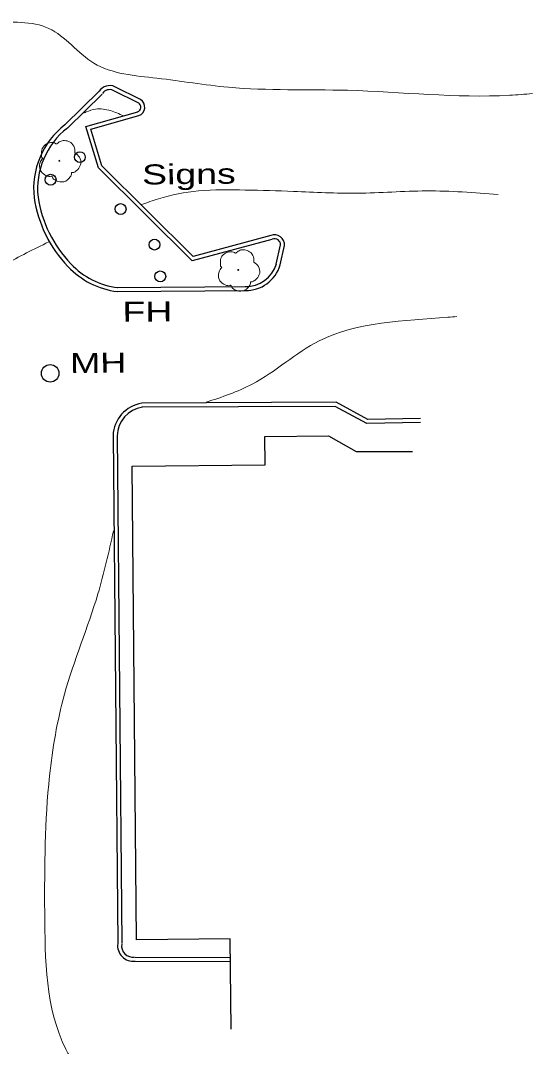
# Model space of a CAD drawing. Extents: x 2361708 to 2370558, y 6977955 to 6991887.
# Drawn here: x 2367606.3 to 2367729.2, y 6988537.8 to 6988783.9 of the extents above; entities that cross this region are included whole.
import ezdxf

# ---------------------------------------------------------------- set-up
doc = ezdxf.new("R2010")
doc.units = 0
doc.header["$LTSCALE"] = 1.9
for name, color, linetype, lineweight in [('11', 7, 'Continuous', 25), ('2', 7, 'Continuous', 25), ('20', 7, 'Continuous', 25), ('21', 7, 'Continuous', 25), ('29', 7, 'Continuous', 13), ('35', 7, 'Continuous', 13)]:
    doc.layers.add(name, color=color, linetype=linetype, lineweight=lineweight)

msp = doc.modelspace()

# ---------------------------------------------------------------- linework, layer by layer
at = {"layer": '11'}
for p, q in [((2367680.208, 6988684.291), (2367686.865, 6988680.534)), ((2367686.865, 6988680.534), (2367700.365, 6988680.552))]:
    msp.add_line(p, q, dxfattribs=at)
msp.add_lwpolyline([(2367656.812, 6988541.951), (2367656.606, 6988563.6), (2367634.167, 6988563.386), (2367633.085, 6988677.052), (2367664.994, 6988677.355), (2367664.929, 6988684.145), (2367680.228, 6988684.291)], dxfattribs=at)
at = {"layer": '2'}
for p, q in [((2367635.108, 6988764.975), (2367628.929, 6988768.046)), ((2367625.179, 6988766.971), (2367616.955, 6988758.902)), ((2367625.856, 6988766.287), (2367617.632, 6988758.218)), ((2367634.677, 6988764.111), (2367628.497, 6988767.182)), ((2367667.675, 6988725.513), (2367668.702, 6988730.133)), ((2367668.618, 6988725.302), (2367669.643, 6988729.922)), ((2367629.497, 6988719.88), (2367661.017, 6988720.14)), ((2367629.506, 6988718.919), (2367661.026, 6988719.18)), ((2367628.505, 6988684.379), (2367629.625, 6988562.493)), ((2367629.465, 6988684.388), (2367630.585, 6988562.502)), ((2367633.786, 6988558.292), (2367656.518, 6988558.199)), ((2367633.787, 6988559.253), (2367656.418, 6988559.158))]:
    msp.add_line(p, q, dxfattribs=at)
for points in [[(2367666.579, 6988731.423), (2367647.487, 6988726.281), (2367624.994, 6988748.558), (2367621.939, 6988758.519), (2367634.426, 6988762.058)], [(2367666.33, 6988732.351), (2367647.767, 6988727.354), (2367625.839, 6988749.066), (2367623.145, 6988757.861), (2367634.685, 6988761.131)], [(2367702.26, 6988688.471), (2367689.631, 6988688.21), (2367682.062, 6988692.339), (2367635.382, 6988692.104)], [(2367702.269, 6988687.511), (2367689.401, 6988687.248), (2367681.821, 6988691.376), (2367635.391, 6988691.144)]]:
    msp.add_lwpolyline(points, dxfattribs=at)
for centre, radius, start, end in [((2367627.684, 6988765.315), 3.002, 65.50588, 146.54301), ((2367627.684, 6988765.315), 2.042, 65.50588, 146.54301), ((2367633.976, 6988763.154), 2.144, 289.30778, 58.12454), ((2367633.976, 6988763.154), 1.184, 289.30778, 58.12454), ((2367628.945, 6988743.516), 19.506, 127.9287, 186.13826), ((2367628.945, 6988743.516), 18.546, 127.9287, 186.13826), ((2367639.582, 6988745.968), 30.371, 188.59108, 223.87594), ((2367639.582, 6988745.968), 29.411, 188.59108, 223.87594), ((2367667.254, 6988730.136), 2.4, 354.89919, 112.62545), ((2367667.254, 6988730.136), 1.44, 354.89919, 112.62545), ((2367631.868, 6988738.213), 18.478, 223.1592, 263.02231), ((2367660.344, 6988727.789), 7.679, 268.81911, 343.27246), ((2367631.868, 6988738.213), 19.438, 223.1592, 263.02231), ((2367660.344, 6988727.789), 8.639, 268.81911, 343.27246), ((2367636.679, 6988684.027), 8.181, 99.1217, 177.53624), ((2367636.679, 6988684.027), 7.221, 99.1217, 177.53624), ((2367633.32, 6988561.992), 3.728, 172.27349, 277.17632), ((2367633.32, 6988561.992), 2.768, 172.27349, 277.17632)]:
    msp.add_arc(centre, radius, start, end, dxfattribs=at)
at = {"layer": '20'}
for centre, radius in [((2367639.832, 6988722.548), 1.3), ((2367613.412, 6988699.296), 2.1)]:
    msp.add_circle(centre, radius, dxfattribs=at)
at = {"layer": '21'}
for centre in [(2367620.539, 6988751.156), (2367613.53, 6988745.739), (2367630.328, 6988738.698), (2367638.45, 6988730.175)]:
    msp.add_circle(centre, 1.3, dxfattribs=at)
at = {"layer": '29'}
for centre in [(2367615.607, 6988750.299), (2367658.549, 6988724.096)]:
    msp.add_circle(centre, 0.1, dxfattribs=at)
for points in [[(2367611.642, 6988750.871), (2367611.661, 6988750.881), (2367611.581, 6988750.951), (2367611.345, 6988751.578), (2367611.383, 6988752.859), (2367612.27, 6988754.157), (2367613.576, 6988754.639), (2367614.697, 6988754.45), (2367614.929, 6988754.322), (2367614.999, 6988754.323), (2367615.048, 6988754.364), (2367615.396, 6988754.657), (2367616.261, 6988755.105), (2367617.472, 6988755.037), (2367618.588, 6988754.447), (2367619.321, 6988753.025), (2367619.33, 6988752.164)], [(2367619.319, 6988752.184), (2367620.46, 6988751.125), (2367620.745, 6988749.538), (2367620.037, 6988748.211), (2367619.382, 6988747.665), (2367618.714, 6988747.448), (2367618.565, 6988747.437), (2367618.545, 6988747.326), (2367618.224, 6988746.424), (2367616.685, 6988745.259), (2367614.793, 6988745.541), (2367613.893, 6988746.482), (2367613.822, 6988746.612), (2367613.702, 6988746.591), (2367612.491, 6988746.709), (2367611.222, 6988747.707), (2367610.876, 6988749.344), (2367611.246, 6988750.367), (2367611.572, 6988750.811), (2367611.642, 6988750.861)], [(2367654.583, 6988724.669), (2367654.603, 6988724.679), (2367654.522, 6988724.748), (2367654.286, 6988725.376), (2367654.324, 6988726.656), (2367655.212, 6988727.955), (2367656.517, 6988728.437), (2367657.639, 6988728.248), (2367657.87, 6988728.12), (2367657.94, 6988728.121), (2367657.99, 6988728.161), (2367658.337, 6988728.454), (2367659.203, 6988728.903), (2367660.414, 6988728.834), (2367661.529, 6988728.245), (2367662.263, 6988726.822), (2367662.271, 6988725.962)], [(2367662.261, 6988725.982), (2367663.401, 6988724.923), (2367663.686, 6988723.335), (2367662.979, 6988722.009), (2367662.324, 6988721.462), (2367661.656, 6988721.246), (2367661.506, 6988721.234), (2367661.487, 6988721.124), (2367661.166, 6988720.221), (2367659.626, 6988719.056), (2367657.734, 6988719.338), (2367656.835, 6988720.28), (2367656.764, 6988720.409), (2367656.644, 6988720.388), (2367655.433, 6988720.507), (2367654.163, 6988721.505), (2367653.818, 6988723.141), (2367654.188, 6988724.165), (2367654.514, 6988724.608), (2367654.583, 6988724.658)]]:
    msp.add_spline(points, degree=3, dxfattribs=at)
at = {"layer": '35'}
for points in [[(2367729.15, 6988766.39), (2367723.693, 6988765.998), (2367684.8, 6988767.188), (2367656.191, 6988767.926), (2367639.03, 6988770.093), (2367623.884, 6988773.739), (2367613.085, 6988782.047), (2367599.332, 6988783.376), (2367583.908, 6988783.609)], [(2367630.955, 6988761.085), (2367627.893, 6988762.316), (2367624.319, 6988762.673), (2367622.066, 6988762.001), (2367621.14, 6988761.622)], [(2367720.889, 6988742.221), (2367703.72, 6988743.057), (2367687.115, 6988742.499), (2367671.83, 6988742.954), (2367660.236, 6988743.263), (2367648.998, 6988743.046), (2367639.385, 6988741.165), (2367635.368, 6988739.766)], [(2367613.063, 6988730.804), (2367602.524, 6988725.293), (2367594.829, 6988719.52), (2367589.098, 6988713.345), (2367584.575, 6988707.311), (2367583.004, 6988704.286)], [(2367711.017, 6988712.935), (2367708.819, 6988712.734), (2367677.961, 6988707.08), (2367661.88, 6988696.687), (2367650.82, 6988692.351)], [(2367583.045, 6988668.415), (2367579.189, 6988656.358), (2367575.703, 6988645.444), (2367574.279, 6988638.51), (2367573.629, 6988624.913), (2367571.673, 6988613.934), (2367571.385, 6988605.261), (2367573.858, 6988591.354), (2367575.811, 6988579.502), (2367578.139, 6988570.244), (2367581.075, 6988557.011), (2367582.995, 6988544.418), (2367583.892, 6988532.177), (2367581.528, 6988512.553), (2367582.181, 6988501.809), (2367585.148, 6988489.557), (2367589.522, 6988479.667), (2367594.049, 6988471.53), (2367600.856, 6988467.705), (2367608.439, 6988467.447), (2367615.482, 6988468.234), (2367619.74, 6988469.535)], [(2367628.613, 6988661.479), (2367624.877, 6988646.372), (2367616.856, 6988622.295), (2367613.261, 6988602.739), (2367612.103, 6988569.997), (2367617.146, 6988537.163), (2367626.323, 6988521.82), (2367632.192, 6988508.265), (2367636.415, 6988501.665), (2367638.5, 6988498.025)]]:
    msp.add_spline(points, degree=3, dxfattribs=at)

# ---------------------------------------------------------------- texts
at = {"layer": '20'}
for s, width, p in [('Signs', 1.4, (2367635.482, 6988744.588)), ('  FH', 1.4, (2367625.776, 6988711.594)), ('  MH', 1.35, (2367613.412, 6988699.296))]:
    msp.add_text(s, height=4.8, rotation=0.545, dxfattribs=dict(at, width=width)).set_placement(p)

doc.saveas('drawing.dxf')
